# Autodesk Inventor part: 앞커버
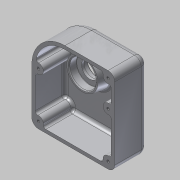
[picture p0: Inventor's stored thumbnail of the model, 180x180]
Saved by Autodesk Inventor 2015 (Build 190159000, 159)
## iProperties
Created: 2015-10
Part Number: 앞커버
Material: 알루미늄 6061
Document SubType Name: Modeling
Designer: mduedu
Density: 2.71 g/cm^3
Mass: 307.08 g
Surface Area: 494.818 cm^2
Volume: 113.314 cm^3
Appearance: Aluminum - Flat
Author: mduedu
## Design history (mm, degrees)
sketch "스케치1"
  geometry: L1 (0, 40)-(60, 40); L2 (60, 40)-(60, -63); L3 (60, -63)-(-40, -63); L4 (-40, -63)-(-40, 0); A1 r 40 centre (0, 0) between (0, 40) and (-40, 0); 1 further point
  constraints: 8 end point, 2 point on circle, 2 tangent, 1 centre point, 1 coincident, 1 horizontal, 1 parallel, 1 perpendicular, 1 vertical
  dimensions: "d0" = 40 radius of A1; "d1" = 103 distance of L1.end L2.end; "d2" = 100 distance of L2.end L3.end
extrude "돌출2" new body sketch "스케치1" distance "d8" = 40; taper "d9" = 0 deg
fillet "모깎기3" dims "d10" = 8
fillet "모깎기4" dims "d11" = 8
feature "쉘2" dims "d12" = 4
sketch "스케치2"
  geometry: C1 r 21.5 at (32, 55); 1 further point
  constraints: 1 centre point, 1 coincident
  dimensions: "d13" = 43 diameter of C1
extrude "돌출3" join sketch "스케치2" distance "d14" = 15; taper "d15" = 0 deg
hole "구멍1" diameter "d18" = 32; stored, may be unused: countersink angle "d22" = 90 deg, drill point angle "d24" = 0 deg; dims "d16" = 10, "d17" = 10, "d19" = 6, "d20" = 4, "d21" = 2, "d23" = 9
hole "구멍2" diameter "d27" = 20; stored, may be unused: countersink angle "d31" = 90 deg, drill point angle "d33" = 0 deg; dims "d25" = 10, "d26" = 10, "d28" = 6, "d29" = 4, "d30" = 2, "d32" = 3
hole "구멍3" diameter "d36" = 25; stored, may be unused: countersink angle "d40" = 90 deg, drill point angle "d42" = 0 deg; dims "d34" = 10, "d35" = 10, "d37" = 6, "d38" = 4, "d39" = 2, "d41" = 3
chamfer "모따기1" distance "d43" = 1; stored, may be unused: second distance "d44" = 2, angle "d45" = 45 deg
feature "면 기울기1" dims angle "d46" = 10 deg
sketch "스케치3"
  geometry: L1 (-40, 0)-(-40, -55) reference; L2 (60, -55)-(60, 32) reference; L3 (-40, 0)-(60, 0); C1 r 6 at (52, 32); C2 r 6 at (52, -55); C3 r 6 at (-32, -55); C4 r 6 at (52, 0); C5 r 6 at (-32, 0); A1 r 8 centre (52, 32) between (60, 32) and (52, 40) reference; A2 r 8 centre (52, -55) between (52, -63) and (60, -55) reference; A3 r 8 centre (-32, -55) between (-40, -55) and (-32, -63) reference; 1 further point
  constraints: 5 centre point, 4 equal radius, 3 coincident, 3 point on line, 2 end point, 2 vertical alignment, 1 perpendicular
  dimensions: "d47" = 6 radius of C1
extrude "돌출4" join sketch "스케치3" stored distance "d49" = 15; taper "d50" = 0 deg
fillet "모깎기5" dims "d51" = 3
fillet "모깎기6" dims "d52" = 3
sketch "스케치4"
  geometry: A1 r 6 centre (-32, 0) between (-32.667, -5.963) and (-31.833, 5.998) reference; A2 r 6 centre (52, 32) between (46.037, 32.667) and (52.667, 26.037) reference; A3 r 6 centre (52, 0) between (52.667, 5.963) and (52.667, -5.963) reference; A4 r 6 centre (52, -55) between (52.667, -49.037) and (46.037, -55.667) reference; A5 r 6 centre (-32, -55) between (-26.037, -55.667) and (-32.667, -49.037) reference; 6 further points
  constraints: 5 coincident
hole "구멍4" sketch "스케치4" at (-32, 0), (52, 32), (52, 0), (52, -55), (-32, -55) diameter "d53" = 3.242; stored, may be unused: countersink angle "d57" = 90 deg, drill point angle "d59" = 118 deg; dims "d54" = 12, "d55" = 4, "d56" = 2, "d58" = 14
sketch "스케치5"
  geometry: L1 (-52, -63)-(32, -63) reference; L2 (-60, 32)-(-60, -55) reference; 2 further points
  constraints: 1 other
  dimensions: "d60" = 20 distance from line of point (-10, -43) L1; "d61" = 50 distance from line of point (-10, -43) L2
feature "엠보싱1" sketch "스케치5" dims "d13" = 43, "d62" = 0.5, "d63" = 0
fillet "모깎기7" dims "d64" = 0.3
node "솔리드2"
